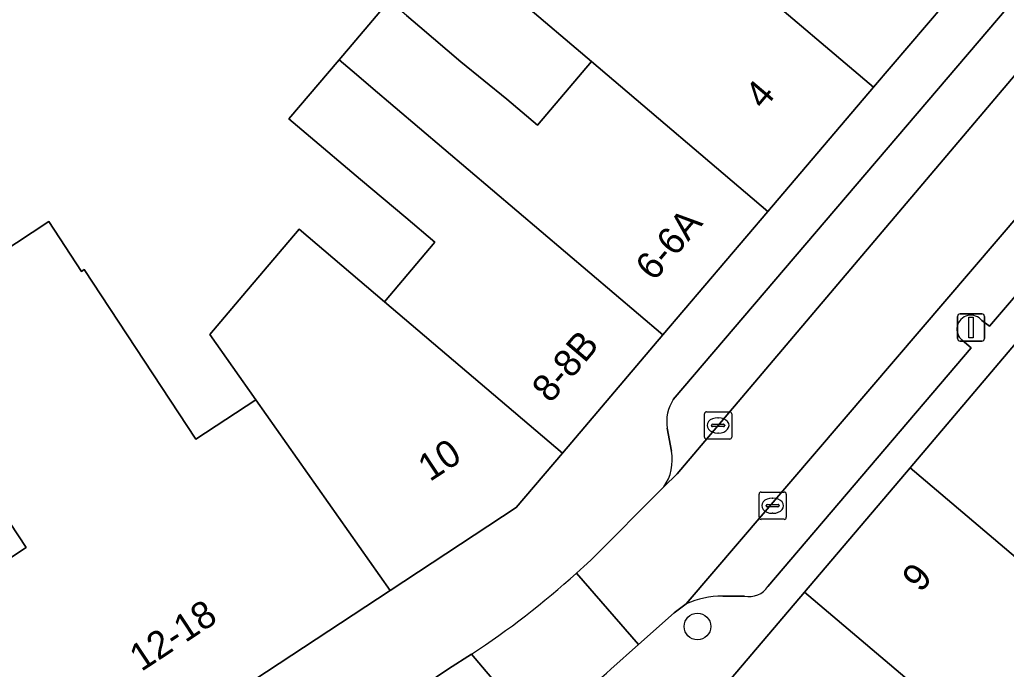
# Model space of a CAD drawing. Extents: x 161798 to 162385, y 382315 to 382833.
# Drawn here: x 162098.63 to 162134.83, y 382608.15 to 382631.99 of the extents above; entities that cross this region are included whole.
import ezdxf

# ---------------------------------------------------------------- set-up
doc = ezdxf.new("R2010")
doc.units = 0
for name, color, linetype in [('IMGEO_Boom', 7, 'Continuous'), ('IMGEO_Erf', 7, 'Continuous'), ('IMGEO_Kolk', 7, 'Continuous'), ('IMGEO_Lichtmast', 7, 'Continuous'), ('IMGEO_Pand', 7, 'Continuous'), ('IMGEO_Pand_nummerreeks', 7, 'Continuous'), ('IMGEO_Parkeervlak_open', 7, 'Continuous'), ('IMGEO_Rijbaan_lokaal_open', 7, 'Continuous'), ('IMGEO_Voetpad_open', 7, 'Continuous')]:
    doc.layers.add(name, color=color, linetype=linetype)

msp = doc.modelspace()

# ---------------------------------------------------------------- linework, layer by layer
at = {"layer": 'IMGEO_Boom'}
msp.add_circle((162123.501, 382609.719), 0.489, dxfattribs=at)
at = {"layer": 'IMGEO_Erf'}
for points in [[(162096.703, 382622.616), (162099.695, 382624.586), (162100.9, 382622.755), (162100.999, 382622.82), (162105.098, 382616.595), (162107.295, 382618.041), (162105.604, 382620.445), (162106.815, 382621.87), (162108.881, 382624.302), (162112.014, 382621.641), (162113.868, 382623.823), (162112.801, 382624.729), (162111.143, 382626.124), (162109.148, 382627.819), (162108.513, 382628.359), (162110.35, 382630.522), (162112.187, 382632.685)], [(162112.822, 382632.146), (162113.31, 382631.732), (162114.819, 382630.45), (162116.502, 382629.075), (162117.627, 382628.119), (162119.612, 382630.456), (162116.961, 382632.708)], [(162096.136, 382610.823), (162098.869, 382612.622), (162093.624, 382620.587)]]:
    msp.add_lwpolyline(points, dxfattribs=at)
at = {"layer": 'IMGEO_Kolk'}
for p, q in [((162123.759, 382616.675), (162123.759, 382617.527)), ((162123.834, 382617.601), (162124.686, 382617.601)), ((162124.76, 382617.527), (162124.76, 382616.675)), ((162124.018, 382617.095), (162124.018, 382617.107)), ((162124.456, 382617.058), (162124.058, 382617.058)), ((162124.061, 382617.144), (162124.459, 382617.144)), ((162124.247, 382617.381), (162124.272, 382617.381)), ((162124.502, 382617.107), (162124.502, 382617.095)), ((162124.27, 382616.821), (162124.245, 382616.821)), ((162124.686, 382616.601), (162123.834, 382616.601)), ((162125.761, 382613.728), (162125.761, 382614.58)), ((162125.836, 382614.654), (162126.688, 382614.654)), ((162126.762, 382614.58), (162126.762, 382613.728)), ((162126.02, 382614.148), (162126.02, 382614.16)), ((162126.063, 382614.197), (162126.461, 382614.197)), ((162126.249, 382614.434), (162126.274, 382614.434)), ((162126.504, 382614.16), (162126.504, 382614.148)), ((162126.458, 382614.111), (162126.06, 382614.111)), ((162126.272, 382613.874), (162126.247, 382613.874)), ((162126.688, 382613.654), (162125.836, 382613.654))]:
    msp.add_line(p, q, dxfattribs=at)
for points in [[(162123.759, 382616.675), (162123.759, 382617.527)], [(162123.834, 382617.601), (162124.686, 382617.601)], [(162124.76, 382617.527), (162124.76, 382616.675)], [(162124.686, 382616.601), (162123.834, 382616.601)], [(162125.761, 382613.728), (162125.761, 382614.58)], [(162125.836, 382614.654), (162126.688, 382614.654)], [(162126.762, 382614.58), (162126.762, 382613.728)], [(162126.688, 382613.654), (162125.836, 382613.654)]]:
    msp.add_lwpolyline(points, dxfattribs=at)
for centre, radius, start, end in [((162123.836, 382617.525), 0.0765, 91.552, 178.448), ((162123.836, 382617.525), 0.0765, 91.552, 178.448), ((162124.684, 382617.525), 0.0765, 1.552, 88.448), ((162124.684, 382617.525), 0.0765, 1.552, 88.448), ((162124.058, 382617.104), 0.0403, 85.8775, 175.7526), ((162124.055, 382617.094), 0.0366, 178.938, 274.7102), ((162124.459, 382617.101), 0.043, 264.8664, 352.4533), ((162124.463, 382617.106), 0.0386, 1.7309, 96.639), ((162123.836, 382616.677), 0.0765, 181.552, 268.448), ((162123.836, 382616.677), 0.0765, 181.552, 268.448), ((162124.684, 382616.677), 0.0765, 271.552, 358.448), ((162124.684, 382616.677), 0.0765, 271.552, 358.448), ((162125.838, 382614.578), 0.0765, 91.552, 178.448), ((162125.838, 382614.578), 0.0765, 91.552, 178.448), ((162126.686, 382614.578), 0.0765, 1.552, 88.448), ((162126.686, 382614.578), 0.0765, 1.552, 88.448), ((162126.06, 382614.157), 0.0403, 85.8775, 175.7526), ((162126.057, 382614.147), 0.0366, 178.938, 274.7102), ((162126.461, 382614.154), 0.043, 264.8664, 352.4533), ((162126.465, 382614.159), 0.0386, 1.7309, 96.639), ((162125.838, 382613.73), 0.0765, 181.552, 268.448), ((162125.838, 382613.73), 0.0765, 181.552, 268.448), ((162126.686, 382613.73), 0.0765, 271.552, 358.448), ((162126.686, 382613.73), 0.0765, 271.552, 358.448)]:
    msp.add_arc(centre, radius, start, end, dxfattribs=at)
for centre, major_axis, ratio, start_param, end_param in [((162124.246, 382617.101), (-0.387, 0.002), 0.722429, 4.712389, 7.853982), ((162124.271, 382617.101), (-0.39, 0.002), 0.717154, 1.570796, 4.712389), ((162126.248, 382614.154), (-0.387, 0.002), 0.722429, 4.712389, 7.853982), ((162126.273, 382614.154), (-0.39, 0.002), 0.717154, 1.570796, 4.712389)]:
    msp.add_ellipse(centre, major_axis=major_axis, ratio=ratio, start_param=start_param, end_param=end_param, dxfattribs=at)
at = {"layer": 'IMGEO_Lichtmast'}
for p, q in [((162133.046, 382620.297), (162133.046, 382621.097)), ((162133.046, 382621.097), (162133.046, 382620.297)), ((162133.146, 382621.197), (162133.936, 382621.197)), ((162133.936, 382621.197), (162133.146, 382621.197)), ((162134.036, 382621.097), (162134.036, 382620.297)), ((162134.036, 382620.297), (162134.036, 382621.097)), ((162133.936, 382620.197), (162133.146, 382620.197)), ((162133.146, 382620.197), (162133.936, 382620.197))]:
    msp.add_line(p, q, dxfattribs=at)
msp.add_lwpolyline([(162133.466, 382621.072), (162133.616, 382621.072), (162133.616, 382620.322), (162133.466, 382620.322), (162133.466, 382621.072)], dxfattribs=at)
for centre, start, end in [((162133.146, 382621.097), 90, 180), ((162133.146, 382621.097), 90, 180), ((162133.936, 382621.097), 0, 90), ((162133.936, 382621.097), 360, 90), ((162133.146, 382620.297), 180, 270), ((162133.146, 382620.297), 180, 270), ((162133.936, 382620.297), 270, 0), ((162133.936, 382620.297), 270, 0)]:
    msp.add_arc(centre, 0.1, start, end, dxfattribs=at)
at = {"layer": 'IMGEO_Pand'}
for points in [[(162127.271, 382639.672), (162125.102, 382637.119), (162123.327, 382638.627), (162123.644, 382639.001), (162120.214, 382641.914), (162118.181, 382639.521), (162120.834, 382637.267), (162129.957, 382629.519), (162133.856, 382634.079)], [(162120.834, 382637.267), (162120.061, 382636.357), (162116.961, 382632.708), (162119.612, 382630.456), (162126.084, 382624.959), (162129.957, 382629.519)], [(162119.612, 382630.456), (162117.627, 382628.119), (162116.502, 382629.075), (162114.819, 382630.45), (162113.31, 382631.732), (162112.822, 382632.146), (162112.187, 382632.685), (162110.35, 382630.522), (162110.985, 382629.982), (162111.512, 382629.534), (162122.235, 382620.427), (162126.084, 382624.959)], [(162111.512, 382629.534), (162110.985, 382629.982), (162110.35, 382630.522), (162108.513, 382628.359), (162109.148, 382627.819), (162111.143, 382626.124), (162112.801, 382624.729), (162113.868, 382623.823), (162112.014, 382621.641), (162118.549, 382616.087), (162122.235, 382620.427)], [(162107.295, 382618.041), (162105.098, 382616.595), (162100.999, 382622.82), (162100.9, 382622.755), (162099.695, 382624.586), (162096.703, 382622.616), (162096.461, 382622.456), (162093.624, 382620.587), (162098.869, 382612.622), (162096.136, 382610.823), (162100.902, 382603.585), (162112.221, 382611.038)], [(162112.014, 382621.641), (162108.881, 382624.302), (162106.815, 382621.87), (162105.604, 382620.445), (162107.295, 382618.041), (162112.221, 382611.038), (162116.85, 382614.086), (162118.549, 382616.087)], [(162141.779, 382614.505), (162141.651, 382614.616), (162135.174, 382620.109), (162131.303, 382615.547), (162142.503, 382606.048), (162142.607, 382605.955), (162142.773, 382606.151), (162143.028, 382606.452), (162144.473, 382608.155), (162142.417, 382609.898), (162140.773, 382611.35), (162139.801, 382612.174)], [(162138.09, 382608.185), (162139.761, 382606.768), (162138.684, 382605.498), (162140.73, 382603.763), (162141.15, 382604.258), (162143.567, 382602.209), (162144.965, 382603.857), (162142.607, 382605.955), (162142.503, 382606.048), (162131.303, 382615.547), (162127.433, 382610.984), (162133.915, 382605.487), (162134.054, 382605.366), (162136.059, 382607.73), (162137.016, 382606.918)], [(162123.564, 382606.422), (162134.825, 382596.872), (162136.697, 382599.078), (162134.647, 382600.817), (162133.592, 382599.574), (162131.977, 382600.944), (162133.05, 382602.209), (162132.076, 382603.035), (162134.054, 382605.366), (162133.915, 382605.487), (162127.433, 382610.984)]]:
    msp.add_lwpolyline(points, close=True, dxfattribs=at)
at = {"layer": 'IMGEO_Parkeervlak_open'}
for points in [[(162122.269, 382614.843), (162122.753, 382615.329), (162149.054, 382646.389)], [(162146.559, 382646.195), (162144.095, 382643.304), (162140.871, 382639.485), (162122.616, 382618.055)], [(162141.201, 382631.731), (162123.083, 382610.549)], [(162133.942, 382620.952), (162134.222, 382620.75), (162140.862, 382628.504)], [(162126.091, 382611.188), (162133.552, 382619.948), (162133.221, 382620.226)], [(162122.391, 382617), (162122.546, 382616.151)], [(162124.429, 382610.839), (162125.228, 382610.829)]]:
    msp.add_lwpolyline(points, dxfattribs=at)
for centre, radius, start, end in [((162133.538, 382620.632), 0.515, 38.4258, 231.9701), ((162123.883, 382617.233), 1.51, 147.0294, 188.8924), ((162120.847, 382615.827), 1.729, 325.3, 10.7859), ((162125.385, 382611.669), 0.854, 259.4161, 325.7577), ((162124.465, 382607.401), 3.438, 90.6074, 113.71)]:
    msp.add_arc(centre, radius, start, end, dxfattribs=at)
at = {"layer": 'IMGEO_Rijbaan_lokaal_open'}
for points in [[(162149.787, 382647.279), (162149.054, 382646.389), (162122.753, 382615.329), (162122.269, 382614.843), (162119.59, 382612.152), (162119.338, 382611.918), (162119.058, 382611.678), (162121.344, 382609.054), (162122.651, 382610.22), (162122.988, 382610.477), (162123.083, 382610.549), (162141.201, 382631.731)], [(162120.329, 382608.149), (162121.344, 382609.054), (162119.058, 382611.678)], [(162115.212, 382608.704), (162117.507, 382605.989)]]:
    msp.add_lwpolyline(points, dxfattribs=at)
msp.add_lwpolyline([(162092.248, 382589.524), (162104.523, 382597.511), (162105.299, 382598.022), (162110.359, 382601.34), (162114.877, 382604.291), (162116.651, 382605.458), (162117.507, 382605.989), (162115.212, 382608.704), (162114.363, 382608.167), (162111.73, 382606.38), (162087.354, 382590.455), (162084.185, 382588.365), (162081.034, 382586.287), (162076.577, 382583.348), (162073.44, 382581.279), (162072.819, 382580.871), (162059.815, 382572.377), (162058.317, 382571.409), (162057.794, 382571.198), (162059.667, 382568.154), (162060.796, 382568.889), (162061.354, 382569.255), (162085.399, 382585.021), (162090.951, 382588.681)], close=True, dxfattribs=at)
for centre, radius, start, end in [((162098.38, 382634.446), 30.756, 303.1806, 312.2469), ((162104.787, 382625.531), 23.318, 303.0606, 311.8013)]:
    msp.add_arc(centre, radius, start, end, dxfattribs=at)
at = {"layer": 'IMGEO_Voetpad_open'}
for points in [[(162150.085, 382647.684), (162147.319, 382649.725), (162134.661, 382635.1), (162133.856, 382634.079), (162129.957, 382629.519), (162126.084, 382624.959), (162122.235, 382620.427), (162118.549, 382616.087), (162116.85, 382614.086), (162112.221, 382611.038), (162100.902, 382603.585), (162099.233, 382602.459), (162093.646, 382598.873)], [(162122.616, 382618.055), (162140.871, 382639.485), (162144.095, 382643.304), (162146.559, 382646.195)], [(162088.523, 382582.702), (162089.165, 382581.708), (162091.498, 382583.245), (162093.517, 382584.575), (162100.557, 382589.214), (162099.697, 382590.512), (162104.937, 382593.957), (162104.785, 382594.155), (162112.146, 382598.926), (162116.822, 382602.004), (162119.59, 382603.578), (162123.441, 382606.277), (162123.564, 382606.422), (162127.433, 382610.984), (162131.303, 382615.547), (162135.174, 382620.109), (162139.044, 382624.672), (162142.914, 382629.235), (162146.784, 382633.798), (162150.752, 382638.476), (162151.434, 382639.358), (162155.256, 382643.887), (162152.892, 382645.592)], [(162140.862, 382628.504), (162134.222, 382620.75), (162133.942, 382620.952)], [(162133.221, 382620.226), (162133.552, 382619.948), (162126.091, 382611.188)], [(162122.546, 382616.151), (162122.391, 382617)], [(162119.058, 382611.678), (162119.338, 382611.918), (162119.59, 382612.152), (162122.269, 382614.843)], [(162123.083, 382610.549), (162122.988, 382610.477), (162122.651, 382610.22), (162121.344, 382609.054), (162120.329, 382608.149)], [(162125.228, 382610.829), (162124.429, 382610.839)], [(162111.73, 382606.38), (162114.363, 382608.167), (162115.212, 382608.704)]]:
    msp.add_lwpolyline(points, dxfattribs=at)
for centre, radius, start, end in [((162133.538, 382620.632), 0.515, 38.4258, 231.9701), ((162123.883, 382617.233), 1.51, 147.0294, 188.8924), ((162120.847, 382615.827), 1.729, 325.3, 10.7859), ((162098.38, 382634.446), 30.756, 303.1806, 312.2469), ((162125.385, 382611.669), 0.854, 259.4161, 325.7577), ((162124.465, 382607.401), 3.438, 90.6074, 113.71), ((162104.787, 382625.531), 23.318, 303.0606, 311.8013)]:
    msp.add_arc(centre, radius, start, end, dxfattribs=at)

# ---------------------------------------------------------------- texts
at = {"layer": 'IMGEO_Pand_nummerreeks'}
for s, rotation, p in [('4', 49.6583, (162125.921, 382628.66)), ('6-6A', 49.6583, (162121.908, 382622.36)), ('8-8B', 49.6583, (162118.107, 382617.884)), ('10', 33.3633, (162113.679, 382615.015)), ('9', 49.6984, (162131.693, 382610.933)), ('12-18', 33.3633, (162103.094, 382608.045))]:
    msp.add_text(s, height=1, rotation=rotation, dxfattribs=at).set_placement(p)

doc.saveas('drawing.dxf')
